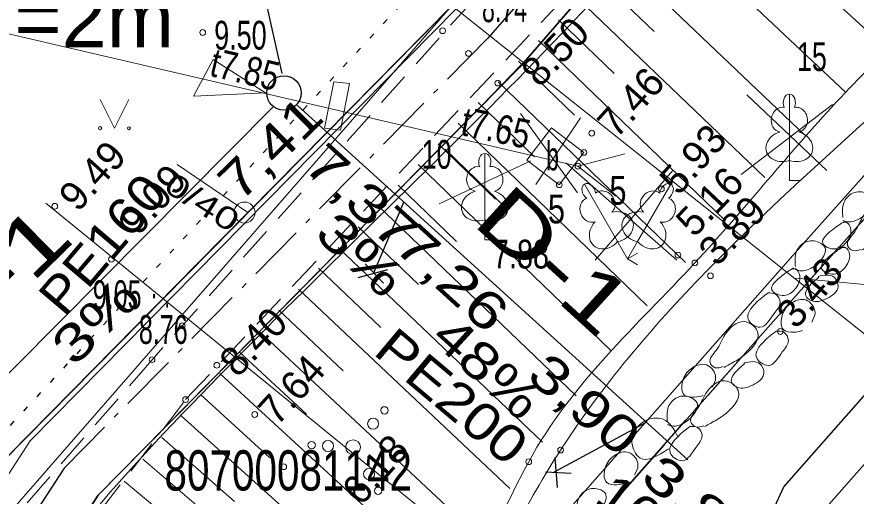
# Model space of a CAD drawing. Extents: x -1320 to -1174, y 762 to 862.
# Drawn here: x -1259.56 to -1244.99, y 803.46 to 811.79 of the extents above; entities that cross this region are included whole.
import ezdxf
from ezdxf.enums import TextEntityAlignment as Align

# ---------------------------------------------------------------- set-up
doc = ezdxf.new("R2010")
doc.units = 0
doc.header["$LTSCALE"] = 0.2
for name, pattern in [('DOT_DASHED', [7.7, 5, -1.2, 0.3, -1.2]), ('DOTTED', [1.5, 0.3, -1.2]), ('MEDIUM_DASHED', [4.5, 3, -1.5])]:
    doc.linetypes.add(name, pattern=pattern)
for name, color, linetype, lineweight in [('1', 7, 'Continuous', 13), ('11', 7, 'Continuous', 35), ('12', 7, 'Continuous', 13), ('19', 7, 'Continuous', 25), ('28', 7, 'Continuous', 13), ('3', 7, 'Continuous', 13), ('35', 7, 'Continuous', 25), ('5', 7, 'Continuous', 13), ('55', 7, 'Continuous', 13), ('56', 7, 'Continuous', 13), ('57', 7, 'DOTTED', 13), ('6', 7, 'Continuous', 13), ('61', 7, 'Continuous', 13), ('62', 7, 'Continuous', 13), ('63', 7, 'Continuous', 13)]:
    doc.layers.add(name, color=color, linetype=linetype, lineweight=lineweight)
for name, color, linetype in [('14', 7, 'Continuous'), ('15', 7, 'Continuous'), ('8', 7, 'Continuous')]:
    doc.layers.add(name, color=color, linetype=linetype)

msp = doc.modelspace()

# ---------------------------------------------------------------- linework, layer by layer
at = {"layer": '1'}
for p, q in [((-1256.057, 815.213), (-1242.15, 804.124)), ((-1247.751, 814.276), (-1244.455, 811.216)), ((-1248.434, 813.546), (-1245.172, 810.47)), ((-1249.122, 812.819), (-1245.881, 809.729)), ((-1249.467, 812.458), (-1248.496, 811.529)), ((-1249.813, 812.097), (-1246.578, 808.992)), ((-1250.16, 811.736), (-1249.19, 810.802)), ((-1250.507, 811.376), (-1247.272, 808.252)), ((-1250.854, 811.017), (-1249.883, 810.076)), ((-1251.202, 810.658), (-1247.957, 807.516)), ((-1251.55, 810.298), (-1250.572, 809.352)), ((-1251.897, 809.939), (-1248.619, 806.764)), ((-1252.245, 809.58), (-1251.253, 808.62)), ((-1255.55, 808.386), (-1256.773, 809.22)), ((-1252.593, 809.221), (-1249.252, 805.989)), ((-1252.94, 808.861), (-1251.925, 807.881)), ((-1259.05, 808.547), (-1246.761, 798.528)), ((-1253.287, 808.501), (-1249.852, 805.2)), ((-1253.634, 808.14), (-1252.587, 807.138)), ((-1253.979, 807.779), (-1250.433, 804.399)), ((-1254.324, 807.417), (-1253.243, 806.391)), ((-1254.668, 807.054), (-1251.002, 803.59)), ((-1255.011, 806.69), (-1253.893, 805.638)), ((-1255.353, 806.325), (-1251.557, 802.778)), ((-1255.694, 805.959), (-1254.533, 804.886)), ((-1256.033, 805.592), (-1252.1, 801.969)), ((-1256.37, 805.223), (-1255.167, 804.127)), ((-1256.706, 804.853), (-1252.608, 801.173)), ((-1257.039, 804.48), (-1255.78, 803.368)), ((-1257.367, 804.103), (-1253.05, 800.403)), ((-1257.691, 803.721), (-1256.362, 802.606))]:
    msp.add_line(p, q, dxfattribs=at)
at = {"layer": '1', "lineweight": 35}
msp.add_line((-1254.685, 810.247), (-1247.912, 804.09), dxfattribs=at)
at = {"layer": '1'}
msp.add_circle((-1255.6051, 808.3858), 0.1827, dxfattribs=at)
msp.add_spline([(-1235.8, 825.801), (-1237.913, 825.174), (-1239.203, 823.346), (-1241.709, 821.268), (-1246.557, 815.58), (-1256.526, 805.053), (-1260.592, 799.147), (-1261.416, 795.29), (-1262.742, 791.444), (-1262.206, 785.139)], degree=3, dxfattribs=at)
at = {"layer": '11'}
msp.add_lwpolyline([(-1263.704, 801.524), (-1261.06, 804.221), (-1255.112, 810.218)], dxfattribs=at)
at = {"layer": '19', "lineweight": 13}
msp.add_spline([(-1253.457, 785.393), (-1253.726, 794.104), (-1251.637, 801.373), (-1250.122, 804.26), (-1247.608, 807.348), (-1239.437, 815.545), (-1236.508, 819.221), (-1228.799, 821.851), (-1223.357, 826.161), (-1220.079, 827.95)], degree=3, dxfattribs=at)
at = {"layer": '28'}
msp.add_lwpolyline([(-1249.009, 809.405), (-1249.82, 809.192), (-1249.163, 808.671)], dxfattribs=at)
at = {"layer": '3'}
msp.add_line((-1270.329, 813.961), (-1249.82, 809.192), dxfattribs=at)
at = {"layer": '35'}
msp.add_lwpolyline([(-1264.692, 791.666), (-1263.121, 794.463), (-1262.995, 800.82), (-1256.407, 807.512), (-1249.819, 814.203), (-1245.888, 819.015), (-1242.275, 823.687), (-1240.604, 825.846), (-1237.968, 829.25), (-1236.511, 829.583), (-1228.03, 831.521)], dxfattribs=at)
at = {"layer": '35', "lineweight": 35}
msp.add_lwpolyline([(-1225.362, 830.487), (-1237.056, 827.834), (-1243.981, 818.809), (-1250.833, 810.905), (-1258.147, 803.474), (-1260.339, 800.099), (-1261.472, 796.156), (-1261.529, 794.093), (-1263.29, 790.894)], dxfattribs=at)
at = {"layer": '5'}
for p, q in [((-1246.152, 810.444), (-1246.152, 809.291)), ((-1246.062, 810.212), (-1246.063, 810.213)), ((-1251.437, 809.414), (-1251.437, 808.261)), ((-1246.152, 809.291), (-1246.152, 808.944)), ((-1251.347, 809.182), (-1251.348, 809.183)), ((-1246.152, 808.944), (-1245.952, 808.944)), ((-1249.708, 808.879), (-1249.132, 807.881)), ((-1248.208, 808.879), (-1248.785, 807.881)), ((-1249.514, 808.723), (-1249.516, 808.723)), ((-1248.247, 808.633), (-1248.247, 808.634)), ((-1251.437, 808.261), (-1251.437, 807.914)), ((-1251.437, 807.914), (-1251.237, 807.914)), ((-1249.132, 807.881), (-1248.958, 807.58)), ((-1248.785, 807.881), (-1248.958, 807.58)), ((-1248.958, 807.58), (-1248.785, 807.68)), ((-1248.958, 807.58), (-1248.785, 807.48))]:
    msp.add_line(p, q, dxfattribs=at)
msp.add_lwpolyline([(-1258.111, 810.352), (-1257.861, 809.852), (-1257.611, 810.352)], dxfattribs=at)
for centre, radius in [((-1258.1113, 809.8512), 0.028), ((-1257.6113, 809.8512), 0.0263), ((-1253.178, 804.9495), 0.064), ((-1253.3745, 804.7178), 0.096), ((-1254.4405, 804.3444), 0.064), ((-1254.156, 804.3309), 0.096), ((-1253.722, 804.3102), 0.128), ((-1253.4456, 803.8433), 0.096), ((-1253.2881, 803.554), 0.064)]:
    msp.add_circle(centre, radius, dxfattribs=at)
for centre, major_axis, ratio, start_param, end_param in [((-1246.1516, 810.2942), (0, -0.1499), 0.707107, 3.1453698, 5.2874846), ((-1246.1525, 810.2942), (0, -0.1499), 0.707107, 0.9957007, 3.1378155), ((-1246.2803, 809.9994), (-0.0387, -0.2124), 0.861323, 3.1415927, 6.2831853), ((-1246.0238, 809.9994), (0.0387, -0.2124), 0.861323, 6.2831853, 9.424778), ((-1246.2416, 809.5371), (0.3068, 0.0951), 0.814445, 1.5707963, 4.7520146), ((-1246.0625, 809.5371), (-0.3068, 0.0951), 0.814445, 1.5311707, 4.712389), ((-1251.4366, 809.2642), (0, -0.1499), 0.707107, 3.1453698, 5.2874846), ((-1251.4375, 809.2642), (0, -0.1499), 0.707107, 0.9957007, 3.1378155), ((-1251.3088, 808.9694), (0.0387, -0.2124), 0.861323, 6.2831853, 9.424778), ((-1251.5653, 808.9694), (-0.0387, -0.2124), 0.861323, 3.1415927, 6.2831853), ((-1249.6327, 808.7495), (0.075, -0.1298), 0.707107, 3.1453698, 5.2874846), ((-1249.6334, 808.7491), (0.075, -0.1298), 0.707107, 0.9957007, 3.1378155), ((-1249.3745, 808.5581), (0.1397, -0.1646), 0.861323, 6.2831853, 9.424778), ((-1248.5416, 808.5581), (-0.1397, -0.1646), 0.861323, 3.1415927, 6.2831853), ((-1248.2827, 808.7491), (-0.075, -0.1298), 0.707107, 3.1453698, 5.2874846), ((-1248.2834, 808.7495), (-0.075, -0.1298), 0.707107, 0.9957007, 3.1378155), ((-1251.5266, 808.5071), (0.3068, 0.0951), 0.814445, 1.5707963, 4.7520146), ((-1251.3475, 808.5071), (-0.3068, 0.0951), 0.814445, 1.5311707, 4.712389), ((-1249.5968, 808.4298), (0.0727, -0.2033), 0.861323, 3.1415927, 6.2831853), ((-1248.3193, 808.4298), (-0.0727, -0.2033), 0.861323, 6.2831853, 9.424778), ((-1249.1769, 808.1384), (-0.3133, -0.071), 0.814445, 1.5311707, 4.712389), ((-1248.7392, 808.1384), (0.3133, -0.071), 0.814445, 1.5707963, 4.7520146), ((-1249.3321, 808.0488), (0.2182, 0.2358), 0.814445, 1.5707963, 4.7520146), ((-1248.584, 808.0488), (-0.2182, 0.2358), 0.814445, 1.5311707, 4.712389)]:
    msp.add_ellipse(centre, major_axis=major_axis, ratio=ratio, start_param=start_param, end_param=end_param, dxfattribs=at)
at = {"layer": '55'}
for points in [[(-1279.323, 790.175), (-1264.692, 791.666), (-1263.121, 794.463), (-1263.06, 799.299), (-1247.785, 816.834), (-1237.845, 829.32), (-1225.799, 831.912), (-1223.768, 834.184)], [(-1251.178, 781.943), (-1250.876, 788.586), (-1249.424, 796.058), (-1246.365, 802.296), (-1239.008, 810.653), (-1237.317, 812.435), (-1234.783, 813.781), (-1227.269, 819.96), (-1220.231, 823.644), (-1218.172, 824.289), (-1214.858, 828.794), (-1213.694, 830.71)]]:
    msp.add_lwpolyline(points, dxfattribs=at)
at = {"layer": '56'}
msp.add_lwpolyline([(-1250.144, 808.869), (-1249.717, 809.43), (-1250.278, 809.857), (-1250.705, 809.296)], close=True, dxfattribs=at)
at = {"layer": '57', "lineweight": 25}
msp.add_line((-1252.899, 811.989), (-1263.665, 800.388), dxfattribs=at)
at = {"layer": '6'}
for centre in [(-1256.3313, 811.5129), (-1252.1678, 811.5445), (-1251.719, 811.1502), (-1251.21, 810.6352), (-1249.581, 809.7642), (-1249.717, 809.4302), (-1249.82, 809.1922), (-1250.144, 808.8691), (-1248.372, 808.7962), (-1258.8979, 808.4944), (-1257.9156, 807.5739), (-1248.085, 807.6472), (-1247.791, 807.5112), (-1247.522, 807.2882), (-1256.687, 806.4182), (-1246.309, 806.3192), (-1257.209, 805.8302), (-1256.086, 805.7322), (-1256.627, 805.1362), (-1255.429, 804.8772), (-1250.122, 804.2602), (-1250.675, 804.0582), (-1254.926, 803.9701)]:
    msp.add_circle(centre, 0.05, dxfattribs=at)
at = {"layer": '61'}
msp.add_lwpolyline([(-1277.32, 790.394), (-1264.695, 791.67), (-1263.123, 794.51), (-1262.995, 800.82), (-1249.819, 814.203)], dxfattribs=at)
at = {"layer": '62'}
msp.add_spline([(-1254.434, 786.21), (-1255.853, 794.247), (-1253.373, 799.783), (-1252.196, 801.907), (-1252.103, 801.965), (-1250.675, 804.058), (-1247.791, 807.511), (-1245.419, 810.213), (-1244.186, 811.494), (-1242.939, 812.764), (-1240.149, 815.75), (-1236.129, 820.169), (-1233.075, 822.242), (-1235.394, 825.816)], degree=3, dxfattribs=at)
at = {"layer": '63', "lineweight": 25}
for p, q in [((-1254.953, 810.799), (-1255.301, 812.357)), ((-1252.841, 808.57), (-1253.374, 807.324)), ((-1253.514, 807.495), (-1253.194, 807.157)), ((-1253.122, 807.392), (-1253.638, 807.25)), ((-1248.648, 804.736), (-1250.244, 803.869)), ((-1250.219, 804.129), (-1250.182, 803.612)), ((-1250.383, 803.883), (-1249.94, 803.858))]:
    msp.add_line(p, q, dxfattribs=at)
at = {"layer": '63'}
for p, q in [((-1246.889, 810.432), (-1245.504, 809.115)), ((-1246.991, 809.047), (-1245.403, 810.263)), ((-1250.815, 810.105), (-1249.827, 808.729)), ((-1249.777, 810.029), (-1250.554, 808.872)), ((-1252.126, 809.486), (-1251.045, 808.439)), ((-1250.639, 809.283), (-1252.227, 808.54)), ((-1250.031, 809.25), (-1248.105, 807.56)), ((-1248.173, 809.115), (-1249.524, 807.56))]:
    msp.add_line(p, q, dxfattribs=at)
at = {"layer": '63', "lineweight": 25}
msp.add_lwpolyline([(-1251.428, 785.238), (-1264.287, 784.95), (-1270.386, 788.761), (-1278.142, 789.522), (-1278.429, 820.376), (-1260.692, 834.371), (-1258.181, 840.695), (-1250.014, 845.483), (-1229.719, 840.992), (-1227.821, 835.408), (-1218.992, 825.806), (-1239.144, 811.691), (-1246.246, 803.626), (-1250.024, 795.415), (-1251.371, 785.665)], close=True, dxfattribs=at)
at = {"layer": '63'}
for points in [[(-1262.966, 796.388), (-1261.719, 800.729), (-1259.323, 804.418), (-1255.629, 808.17), (-1251.935, 811.923), (-1248.539, 815.84), (-1245.143, 819.757), (-1241.53, 824.466), (-1237.916, 829.176), (-1231.805, 830.562), (-1225.694, 831.949), (-1225.362, 830.487), (-1237.053, 827.834), (-1240.518, 823.322), (-1243.326, 819.676), (-1247.407, 814.857), (-1250.833, 810.905), (-1254.833, 806.84), (-1258.147, 803.474), (-1260.348, 800.104), (-1261.483, 796.15)], [(-1261.483, 796.15), (-1260.348, 800.104), (-1258.147, 803.474), (-1257.342, 804.291), (-1256.78, 804.862), (-1256.04, 805.612), (-1253.626, 808.067), (-1251.48, 810.249), (-1250.651, 811.111), (-1250.414, 811.388), (-1248.806, 813.242), (-1245.075, 817.511), (-1244.093, 818.684), (-1242.558, 820.667), (-1241.555, 821.963), (-1239.557, 824.569), (-1237.053, 827.834), (-1230.901, 829.229)], [(-1231.863, 823.367), (-1235.734, 819.766), (-1239.521, 815.019), (-1242.918, 811.201), (-1245.916, 807.839), (-1248.699, 804.681), (-1251.078, 801.983), (-1252.85, 799.838), (-1253.787, 798.196), (-1254.328, 797.239), (-1254.328, 797.239), (-1255.102, 794.624)], [(-1228.737, 806.576), (-1238.728, 806.576), (-1246.038, 807.247)]]:
    msp.add_lwpolyline(points, dxfattribs=at)
at = {"layer": '63', "linetype": 'MEDIUM_DASHED'}
for points in [[(-1265.079, 785.987), (-1263.807, 789.442), (-1261.536, 795.397), (-1260.86, 799.605), (-1256.627, 805.136), (-1246.564, 815.823), (-1241.769, 821.378), (-1239.214, 823.453), (-1237.177, 827.558), (-1234.848, 828.79), (-1231.517, 829.195), (-1224.557, 831.447)], [(-1247.437, 816.79), (-1257.209, 805.83), (-1262.318, 799.97), (-1262.654, 795.375), (-1263.503, 792.223), (-1265.015, 790.631), (-1268.643, 788.504)]]:
    msp.add_lwpolyline(points, dxfattribs=at)
at = {"layer": '63', "linetype": 'DOT_DASHED', "lineweight": 25}
for points in [[(-1225.528, 831.218), (-1237.486, 828.505), (-1244.562, 819.283), (-1251.384, 811.414), (-1258.735, 803.946), (-1261.029, 800.414), (-1262.219, 796.272), (-1262.274, 794.295), (-1264.33, 790.56), (-1266.742, 787.222)], [(-1254.918, 786.26), (-1254.605, 794.542), (-1253.865, 797.042), (-1252.437, 799.553), (-1250.698, 801.658), (-1245.95, 807.041), (-1239.139, 814.697), (-1235.363, 819.429), (-1232.239, 822.444), (-1231.619, 822.931), (-1231.44, 822.991), (-1229.31, 823.677), (-1223.125, 826.536)]]:
    msp.add_lwpolyline(points, dxfattribs=at)
at = {"layer": '63', "lineweight": 35}
msp.add_lwpolyline([(-1254.918, 786.26), (-1254.605, 794.542), (-1253.865, 797.042), (-1252.437, 799.553), (-1251.568, 800.606), (-1250.698, 801.658), (-1248.324, 804.35), (-1245.95, 807.041), (-1242.544, 810.869), (-1239.139, 814.697), (-1237.251, 817.063), (-1235.363, 819.429), (-1233.801, 820.936), (-1232.239, 822.444), (-1231.619, 822.931), (-1229.31, 823.677), (-1223.125, 826.536)], dxfattribs=at)
at = {"layer": '63'}
for points in [[(-1255.242, 810.466), (-1256.147, 811.045), (-1256.492, 810.405)], [(-1254.054, 810.656), (-1254.216, 809.853), (-1253.94, 809.819), (-1253.786, 810.625)]]:
    msp.add_lwpolyline(points, close=True, dxfattribs=at)
at = {"layer": '63', "lineweight": 25}
msp.add_circle((-1254.9212, 810.4632), 0.3, dxfattribs=at)
at = {"layer": '63'}
for points in [[(-1245.224, 808.299), (-1245.208, 808.552), (-1245.051, 808.722), (-1244.81, 808.717), (-1244.707, 808.621), (-1244.787, 808.404), (-1244.922, 808.285), (-1245.145, 808.226), (-1245.222, 808.25)], [(-1244.913, 807.745), (-1245.051, 807.727), (-1245.142, 807.812), (-1245.036, 808.028), (-1244.883, 808.3), (-1244.551, 808.527), (-1244.319, 808.358), (-1244.579, 807.921), (-1244.801, 807.787), (-1244.9, 807.732)], [(-1245.196, 808.231), (-1245.405, 808.088), (-1245.573, 807.853), (-1245.355, 807.753), (-1245.171, 807.862), (-1245.087, 808.097), (-1245.162, 808.214), (-1245.221, 808.214)], [(-1246.048, 807.449), (-1246.032, 807.702), (-1245.875, 807.872), (-1245.634, 807.867), (-1245.531, 807.771), (-1245.611, 807.554), (-1245.746, 807.435), (-1245.969, 807.376), (-1246.046, 807.4)], [(-1245.217, 807.794), (-1245.426, 807.651), (-1245.594, 807.416), (-1245.376, 807.316), (-1245.192, 807.425), (-1245.108, 807.66), (-1245.183, 807.777), (-1245.242, 807.777)], [(-1246.081, 807.424), (-1246.29, 807.281), (-1246.458, 807.046), (-1246.24, 806.946), (-1246.056, 807.055), (-1245.972, 807.29), (-1246.047, 807.407), (-1246.106, 807.407)], [(-1245.654, 807.276), (-1245.376, 807.261), (-1245.306, 807.1), (-1245.501, 806.892), (-1245.775, 806.856), (-1245.867, 806.94), (-1245.773, 807.145), (-1245.639, 807.263)], [(-1246.522, 806.99), (-1246.742, 806.805), (-1246.869, 806.536), (-1246.663, 806.393), (-1246.419, 806.629), (-1246.314, 806.823), (-1246.395, 806.97), (-1246.522, 806.99)], [(-1245.765, 806.481), (-1245.707, 806.647), (-1245.867, 806.868), (-1246.105, 806.821), (-1246.272, 806.614), (-1246.251, 806.349), (-1246.073, 806.306), (-1245.922, 806.337)], [(-1247.299, 805.709), (-1247.437, 805.691), (-1247.528, 805.776), (-1247.422, 805.992), (-1247.269, 806.264), (-1246.937, 806.491), (-1246.705, 806.322), (-1246.965, 805.885), (-1247.187, 805.751), (-1247.286, 805.696)], [(-1246.378, 806.328), (-1246.598, 806.143), (-1246.725, 805.874), (-1246.519, 805.731), (-1246.275, 805.967), (-1246.17, 806.161), (-1246.251, 806.308), (-1246.378, 806.328)], [(-1247.489, 805.353), (-1247.431, 805.519), (-1247.591, 805.74), (-1247.829, 805.693), (-1247.996, 805.486), (-1247.975, 805.221), (-1247.797, 805.178), (-1247.646, 805.209)], [(-1246.941, 805.774), (-1246.663, 805.759), (-1246.593, 805.598), (-1246.788, 805.39), (-1247.062, 805.354), (-1247.154, 805.438), (-1247.06, 805.643), (-1246.926, 805.761)], [(-1247.635, 804.682), (-1247.773, 804.664), (-1247.864, 804.749), (-1247.758, 804.965), (-1247.605, 805.237), (-1247.273, 805.464), (-1247.041, 805.295), (-1247.301, 804.858), (-1247.523, 804.724), (-1247.622, 804.669)], [(-1248.269, 804.752), (-1248.253, 805.005), (-1248.096, 805.175), (-1247.855, 805.17), (-1247.752, 805.074), (-1247.832, 804.857), (-1247.967, 804.738), (-1248.19, 804.679), (-1248.267, 804.703)], [(-1248.082, 804.484), (-1248.344, 804.797), (-1248.67, 804.759), (-1248.883, 804.399), (-1248.747, 804.126), (-1248.248, 804.282)], [(-1247.874, 804.672), (-1248.094, 804.487), (-1248.221, 804.218), (-1248.015, 804.075), (-1247.771, 804.311), (-1247.666, 804.505), (-1247.747, 804.652), (-1247.874, 804.672)], [(-1248.837, 803.832), (-1248.779, 803.998), (-1248.939, 804.219), (-1249.177, 804.172), (-1249.344, 803.965), (-1249.323, 803.7), (-1249.145, 803.657), (-1248.994, 803.688)], [(-1249.805, 803.104), (-1249.829, 803.356), (-1249.7, 803.549), (-1249.462, 803.582), (-1249.345, 803.503), (-1249.39, 803.276), (-1249.505, 803.137), (-1249.716, 803.044), (-1249.795, 803.056)]]:
    msp.add_spline(points, degree=3, dxfattribs=at)

# ---------------------------------------------------------------- texts
at = {"layer": '1', "width": 1.4}
msp.add_text('0/40', height=0.384, rotation=327.602, dxfattribs=at).set_placement((-1256.4434, 808.402), align=Align.CENTER)
at = {"layer": '11'}
for s, height, rotation, width, p in [('t7.85', 0.5, 346.91, 0.8, (-1255.6521, 810.6293)), ('t7.65', 0.5, 348.15, 0.8, (-1251.2933, 809.6133)), ('D-1', 1, 317.647, 1.4, (-1250.5608, 807.181))]:
    msp.add_text(s, height=height, rotation=rotation, dxfattribs=dict(at, width=width)).set_placement(p, align=Align.CENTER)
at = {"layer": '12'}
for s, width, p in [(' 15', 0.7, (-1246.152, 810.844)), (' 10', 0.7, (-1252.664, 809.147)), (' 5', 0.8, (-1249.424, 808.522)), (' 5', 0.8, (-1250.491, 808.198))]:
    msp.add_text(s, height=0.5, dxfattribs=dict(at, width=width)).set_placement(p)
at = {"layer": '14', "width": 0.75}
msp.add_text('80700081142', height=0.7, dxfattribs=at).set_placement((-1256.995, 803.557))
at = {"layer": '15', "width": 0.6}
msp.add_text('b', height=0.5, dxfattribs=at).set_placement((-1250.374, 809.117))
at = {"layer": '63', "width": 1.05}
msp.add_text('PE600, l=2m', height=1, dxfattribs=at).set_placement((-1260.868, 811.258), align=Align.CENTER)
at = {"layer": '63'}
for s, height, rotation, width, p in [('7,41', 0.64, 44.434, 1.25, (-1254.939, 809.2764)), ('7,37', 0.64, 317.647, 1.35, (-1253.7901, 808.4137)), ('PE160', 0.64, 49.693, 1.1, (-1257.8232, 807.6315)), ('3%', 0.64, 317.647, 1.35, (-1253.8011, 807.4193)), ('D-1', 1, 44.437, 1.45, (-1259.6461, 806.8064)), ('7,26', 0.64, 317.647, 1.35, (-1252.2196, 807.0095)), ('3%', 0.64, 44.434, 1.35, (-1257.969, 806.2755)), ('PE200', 0.64, 319.946, 1.2, (-1252.2159, 804.9487)), ('48%', 0.64, 317.647, 1.25, (-1251.6041, 805.4565)), ('3,90', 0.64, 319.946, 1.3, (-1249.9094, 804.8103)), ('3,80', 0.64, 319.946, 1.35, (-1247.9039, 803.0174)), ('10%', 0.64, 323.374, 1.15, (-1248.7684, 802.7901))]:
    msp.add_text(s, height=height, rotation=rotation, dxfattribs=dict(at, width=width)).set_placement(p, align=Align.CENTER)
at = {"layer": '8'}
for s, width, p in [('8.74', 0.6, (-1251.485, 811.693)), ('9.50', 0.7, (-1256.132, 811.216)), (' 7.88', 0.75, (-1251.437, 807.414)), ('9.05', 0.65, (-1258.238, 806.71)), ('.', 0.5, (-1257.224, 806.893)), ('.', 0.5, (-1256.993, 806.733)), ('8.76', 0.65, (-1257.438, 806.104))]:
    msp.add_text(s, height=0.5, dxfattribs=dict(at, width=width)).set_placement(p)
for s, rotation, p in [(' 8.50', 46.059, (-1250.616, 810.406)), (' 7.46', 48.037, (-1249.276, 809.514)), (' 5.93', 48.163, (-1248.197, 808.525)), ('9.49', 47.907, (-1258.497, 808.376)), ('9.09', 47.907, (-1257.447, 807.967)), (' 5.16', 46.615, (-1247.93, 807.8)), (' 3.89', 46.961, (-1247.532, 807.295)), (' 3.43', 49.314, (-1246.156, 806.2)), (' 8.40', 45.78, (-1255.857, 805.37)), (' 7.64', 47.838, (-1255.165, 804.524)), (' 6.18', 48.595, (-1253.704, 803.132))]:
    msp.add_text(s, height=0.5, rotation=rotation, dxfattribs=at).set_placement(p)

doc.saveas('drawing.dxf')
